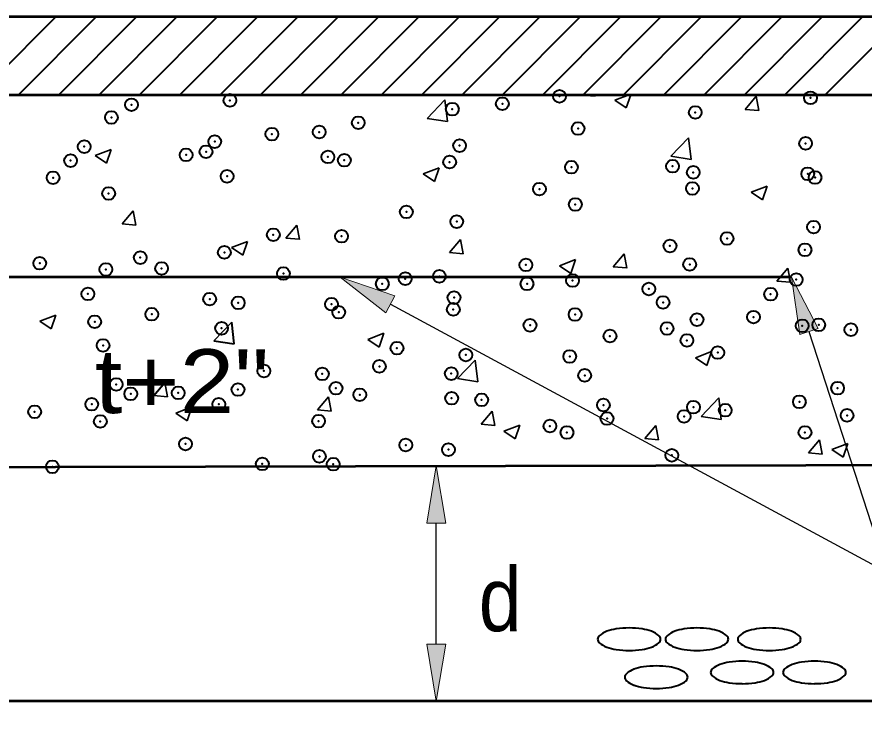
# Model space of a CAD drawing. Extents: x 36.4 to 71.7, y 0.5 to 22.5.
# Drawn here: x 50.926 to 52.782, y 8.551 to 10.106 of the extents above; entities that cross this region are included whole.
import ezdxf

# ---------------------------------------------------------------- set-up
doc = ezdxf.new("R2010")
doc.units = 0
doc.header["$LTSCALE"] = 0.056
doc.header["$PDMODE"] = 32
doc.header["$PDSIZE"] = 0.028
for name, color, linetype, lineweight in [('1', 7, 'Continuous', 40), ('3', 7, 'Continuous', 13), ('6', 7, 'Continuous', 13)]:
    doc.layers.add(name, color=color, linetype=linetype, lineweight=lineweight)

msp = doc.modelspace()

# ---------------------------------------------------------------- hatches: boundary and pattern name
at = {"layer": '1'}
for points in [[(51.86592, 8.99758), (51.82425, 8.99758), (51.84508, 9.12258), (51.84508, 9.12258)], [(51.86592, 8.73225), (51.82425, 8.73225), (51.84508, 8.60725), (51.84508, 8.60725)]]:
    msp.add_hatch(color=256, dxfattribs=at).paths.add_polyline_path(points)
at = {"layer": '3'}
for points in [[(51.73492, 9.45833), (51.75467, 9.495), (51.63483, 9.53608), (51.63483, 9.53608)], [(52.642, 9.41075), (52.68167, 9.42358), (52.62333, 9.53608), (52.62333, 9.53608)]]:
    msp.add_hatch(color=256, dxfattribs=at).paths.add_polyline_path(points)

# ---------------------------------------------------------------- linework, layer by layer
at = {"layer": '1', "lineweight": 53}
for p, q in [((53.64358, 10.10608), (47.51525, 10.10608)), ((47.58758, 9.9355), (53.64358, 9.9355)), ((52.62333, 9.53608), (48.61192, 9.53608)), ((53.64175, 8.60725), (50.02825, 8.60725))]:
    msp.add_line(p, q, dxfattribs=at)
at = {"layer": '1'}
for p, q in [((50.841, 9.9355), (51.01167, 10.10608)), ((50.92942, 9.9355), (51.1, 10.10608)), ((51.01783, 9.9355), (51.18842, 10.10608)), ((51.10617, 9.9355), (51.27683, 10.10608)), ((51.19458, 9.9355), (51.36517, 10.10608)), ((51.283, 9.9355), (51.45358, 10.10608)), ((51.37133, 9.9355), (51.54192, 10.10608)), ((51.45975, 9.9355), (51.63033, 10.10608)), ((51.54817, 9.9355), (51.71875, 10.10608)), ((51.6365, 9.9355), (51.80708, 10.10608)), ((51.72492, 9.9355), (51.8955, 10.10608)), ((51.81333, 9.9355), (51.98392, 10.10608)), ((51.90167, 9.9355), (52.07225, 10.10608)), ((51.99008, 9.9355), (52.16067, 10.10608)), ((52.0785, 9.9355), (52.24908, 10.10608)), ((52.16683, 9.9355), (52.33742, 10.10608)), ((52.25525, 9.9355), (52.42583, 10.10608)), ((52.34367, 9.9355), (52.51425, 10.10608)), ((52.432, 9.9355), (52.60258, 10.10608)), ((52.52042, 9.9355), (52.691, 10.10608)), ((52.60883, 9.9355), (52.77942, 10.10608)), ((52.69717, 9.9355), (52.86775, 10.10608)), ((51.4025, 9.38992), (51.39692, 9.43733)), ((51.358, 9.39675), (51.4025, 9.38992)), ((51.22658, 9.27683), (51.25067, 9.30558))]:
    msp.add_line(p, q, dxfattribs=at)
at = {"layer": '1', "lineweight": 35}
for p, q in [((52.16367, 9.93492), (52.16417, 9.9355)), ((52.16367, 9.93492), (52.19358, 9.93233)), ((52.19358, 9.93233), (52.193, 9.9355)), ((52.23667, 9.92358), (52.26758, 9.9355)), ((52.26158, 9.90683), (52.27117, 9.9355)), ((52.52233, 9.90358), (52.54642, 9.93225)), ((52.55225, 9.90092), (52.54642, 9.93225)), ((51.82533, 9.88383), (51.86425, 9.92442)), ((51.86983, 9.87692), (51.86425, 9.92442)), ((52.23667, 9.92358), (52.26158, 9.90683)), ((52.52233, 9.90358), (52.55217, 9.90092)), ((51.82533, 9.88383), (51.86983, 9.87692)), ((52.35892, 9.80108), (52.39792, 9.84167)), ((52.40342, 9.79417), (52.39792, 9.84167)), ((51.098, 9.80242), (51.133, 9.81583)), ((51.098, 9.80242), (51.12283, 9.78558)), ((51.12292, 9.78558), (51.133, 9.81583)), ((52.35892, 9.80108), (52.40342, 9.79417)), ((51.81658, 9.76233), (51.85158, 9.77575)), ((51.84142, 9.74558), (51.85158, 9.77575)), ((51.81658, 9.76233), (51.84142, 9.74558)), ((52.53517, 9.72233), (52.57017, 9.73575)), ((52.56, 9.7055), (52.57017, 9.73575)), ((52.53517, 9.72233), (52.56, 9.7055)), ((51.15717, 9.65292), (51.18125, 9.68167)), ((51.18708, 9.65033), (51.18125, 9.68167)), ((51.15717, 9.65292), (51.18708, 9.65033)), ((51.51583, 9.62158), (51.53992, 9.65033)), ((51.54567, 9.61892), (51.53992, 9.65033)), ((51.51583, 9.62158), (51.54567, 9.619)), ((51.87442, 9.59017), (51.8985, 9.61892)), ((51.90433, 9.58758), (51.89858, 9.61892)), ((51.39642, 9.60108), (51.4315, 9.6145)), ((51.39642, 9.60108), (51.42133, 9.58433)), ((51.42133, 9.58433), (51.4315, 9.6145)), ((51.87442, 9.59017), (51.90433, 9.58758)), ((52.23308, 9.55883), (52.25717, 9.58758)), ((52.26292, 9.55617), (52.25717, 9.58758)), ((52.115, 9.561), (52.15, 9.5745)), ((52.115, 9.561), (52.13992, 9.54425)), ((52.13992, 9.54425), (52.15, 9.5745)), ((52.23308, 9.55883), (52.26292, 9.55625)), ((52.59167, 9.52742), (52.61583, 9.55617)), ((52.62158, 9.52483), (52.61583, 9.55617)), ((52.59167, 9.52742), (52.62158, 9.52483)), ((50.97633, 9.43983), (51.01133, 9.45325)), ((51.00125, 9.423), (51.01133, 9.45325)), ((50.97633, 9.43983), (51.00125, 9.42308)), ((51.358, 9.39675), (51.39692, 9.43733)), ((51.69492, 9.39975), (51.72992, 9.41325)), ((51.71975, 9.383), (51.72992, 9.41317)), ((51.69492, 9.39975), (51.71975, 9.383)), ((52.4135, 9.35975), (52.4485, 9.37317)), ((52.4135, 9.35975), (52.43833, 9.34292)), ((52.43833, 9.34292), (52.4485, 9.37317)), ((51.89158, 9.314), (51.93058, 9.35458)), ((51.93608, 9.30708), (51.93058, 9.35458)), ((51.25642, 9.27425), (51.25067, 9.30558)), ((51.89158, 9.314), (51.93608, 9.30717)), ((51.22658, 9.27683), (51.25642, 9.27425)), ((51.58517, 9.2455), (51.60925, 9.27425)), ((51.61508, 9.24283), (51.60925, 9.27417)), ((52.42525, 9.23125), (52.46417, 9.27183)), ((52.46975, 9.22433), (52.46417, 9.27183)), ((51.27483, 9.2385), (51.30983, 9.25192)), ((51.29967, 9.22175), (51.30983, 9.25192)), ((51.58517, 9.2455), (51.61508, 9.24283)), ((51.27483, 9.2385), (51.29967, 9.22175)), ((51.94383, 9.21408), (51.96792, 9.24283)), ((51.97367, 9.2115), (51.96792, 9.24283)), ((51.97367, 9.2115), (51.96792, 9.24283)), ((52.42525, 9.23125), (52.46967, 9.22433)), ((51.94383, 9.21408), (51.97367, 9.2115)), ((51.99333, 9.1985), (52.02833, 9.21192)), ((52.01825, 9.18167), (52.02842, 9.21192)), ((52.01825, 9.18167), (52.02842, 9.21192)), ((52.30242, 9.18275), (52.32658, 9.2115)), ((52.33233, 9.18008), (52.32658, 9.21142)), ((51.99333, 9.1985), (52.01825, 9.18167)), ((52.30242, 9.18275), (52.33233, 9.18008)), ((52.66108, 9.15133), (52.68517, 9.18008)), ((52.691, 9.14875), (52.68517, 9.18008)), ((52.71192, 9.15842), (52.74692, 9.17183)), ((52.73683, 9.14167), (52.74692, 9.17183)), ((52.66108, 9.15133), (52.69092, 9.14875)), ((52.71192, 9.15842), (52.73683, 9.14167))]:
    msp.add_line(p, q, dxfattribs=at)
at = {"layer": '1', "lineweight": 13}
for p, q in [((51.86317, 9.12258), (51.66508, 9.12258)), ((51.80275, 8.60725), (51.66508, 8.60725))]:
    msp.add_line(p, q, dxfattribs=at)
at = {"layer": '1', "lineweight": 25}
msp.add_line((51.84508, 8.73225), (51.84508, 8.99758), dxfattribs=at)
at = {"layer": '1', "lineweight": 53}
msp.add_lwpolyline([(47.51525, 10.10608), (43.59017, 10.10608), (43.59017, 9.827), (43.43175, 9.55683), (43.67933, 9.42175), (43.62983, 9.27633), (44.10525, 9.27633), (46.07633, 9.11), (53.64175, 9.12625)], dxfattribs=at)
at = {"layer": '1', "lineweight": 13}
for points in [[(51.86592, 8.99758), (51.82425, 8.99758), (51.84508, 9.12258), (51.84508, 9.12258)], [(51.86592, 8.73225), (51.82425, 8.73225), (51.84508, 8.60725), (51.84508, 8.60725)]]:
    msp.add_lwpolyline(points, close=True, dxfattribs=at)
at = {"layer": '1'}
for centre, radius, start, end in [((52.25558, 8.6585), 0.10836, 98.47139, 109.71022), ((52.26783, 8.57525), 0.19248, 90.02264, 98.43766), ((52.26775, 8.57467), 0.19304, 81.57477, 89.98979), ((52.28, 8.65892), 0.10795, 70.23479, 81.47362), ((52.40408, 8.65892), 0.10795, 98.52638, 109.76521), ((52.41633, 8.57467), 0.19304, 90.0102, 98.42523), ((52.41625, 8.57525), 0.19248, 81.56233, 89.97736), ((52.4285, 8.6585), 0.10836, 70.28977, 81.5286), ((52.56258, 8.6585), 0.10836, 98.47139, 109.71022), ((52.57483, 8.57467), 0.19304, 90.0102, 98.42523), ((52.57475, 8.57525), 0.19248, 81.56233, 89.97736), ((52.587, 8.6585), 0.10836, 70.28977, 81.5286), ((52.209, 8.74308), 0.01025, 130.57008, 179.80152), ((52.20892, 8.74317), 0.01016, 180.43525, 229.6667), ((52.23658, 8.71092), 0.05258, 109.55636, 130.6711), ((52.29892, 8.71092), 0.05258, 49.32889, 70.44364), ((52.32658, 8.74317), 0.01016, 310.3333, 359.56474), ((52.3265, 8.74308), 0.01025, 0.19847, 49.42992), ((52.35758, 8.74308), 0.01025, 130.57008, 179.80152), ((52.3575, 8.74317), 0.01016, 180.43525, 229.6667), ((52.38517, 8.71092), 0.05258, 109.55636, 130.6711), ((52.4475, 8.71092), 0.05258, 49.32889, 70.44364), ((52.47508, 8.74308), 0.01025, 0.19847, 49.42992), ((52.47517, 8.74317), 0.01016, 310.3333, 359.56474), ((52.516, 8.74317), 0.01021, 131.07972, 180.31117), ((52.51592, 8.74308), 0.01012, 179.922, 229.15345), ((52.54358, 8.71092), 0.05258, 109.55636, 130.6711), ((52.606, 8.71092), 0.05258, 49.32889, 70.44364), ((52.63358, 8.74317), 0.01021, 359.68883, 48.92027), ((52.63367, 8.74308), 0.01012, 310.84655, 0.07799), ((52.23683, 8.77525), 0.05269, 229.11499, 250.22974), ((52.25508, 8.82775), 0.10826, 250.5082, 261.74703), ((52.28042, 8.82733), 0.10785, 278.30717, 289.546), ((52.29867, 8.77525), 0.05269, 289.77026, 310.885), ((52.38542, 8.77525), 0.05269, 229.11499, 250.22974), ((52.40367, 8.82733), 0.10785, 250.454, 261.69283), ((52.429, 8.82775), 0.10826, 278.25297, 289.4918), ((52.44725, 8.77525), 0.05269, 289.77026, 310.885), ((52.54383, 8.77525), 0.05269, 229.11499, 250.22974), ((52.56208, 8.82775), 0.10826, 250.5082, 261.74703), ((52.5875, 8.82775), 0.10826, 278.25297, 289.4918), ((52.60575, 8.77525), 0.05269, 289.77026, 310.885), ((52.26783, 8.911), 0.19248, 261.56233, 269.97736), ((52.26775, 8.91158), 0.19304, 270.0102, 278.42523), ((52.41633, 8.91158), 0.19304, 261.57477, 269.98979), ((52.41625, 8.911), 0.19248, 270.02264, 278.43766), ((52.57483, 8.91158), 0.19304, 261.57477, 269.98979), ((52.57475, 8.911), 0.19248, 270.02264, 278.43766), ((52.48417, 8.63817), 0.05258, 109.55636, 130.6711), ((52.50317, 8.58575), 0.10836, 98.47139, 109.71022), ((52.51542, 8.50192), 0.19304, 90.0102, 98.42523), ((52.51533, 8.5025), 0.19248, 81.56233, 89.97736), ((52.52758, 8.58575), 0.10836, 70.28977, 81.5286), ((52.54658, 8.63817), 0.05258, 49.32889, 70.44364), ((52.64267, 8.63817), 0.05258, 109.55636, 130.6711), ((52.66167, 8.58575), 0.10836, 98.47139, 109.71022), ((52.67392, 8.5025), 0.19248, 90.02264, 98.43766), ((52.67383, 8.50192), 0.19304, 81.57477, 89.98979), ((52.68608, 8.58617), 0.10795, 70.23479, 81.47362), ((52.705, 8.63817), 0.05258, 49.32889, 70.44364), ((52.29625, 8.62783), 0.05269, 109.77026, 130.885), ((52.3145, 8.57533), 0.10826, 98.25297, 109.4918), ((52.32725, 8.49208), 0.19248, 90.02264, 98.43766), ((52.32717, 8.4915), 0.19304, 81.57477, 89.98979), ((52.33983, 8.57575), 0.10785, 70.454, 81.69283), ((52.35808, 8.62783), 0.05269, 49.11499, 70.22974), ((52.45658, 8.67042), 0.01021, 131.07972, 180.31117), ((52.4565, 8.67033), 0.01012, 179.922, 229.15345), ((52.57425, 8.67033), 0.01012, 310.84655, 0.07799), ((52.57417, 8.67042), 0.01021, 359.68883, 48.92027), ((52.61508, 8.67042), 0.01021, 131.07972, 180.31117), ((52.615, 8.67033), 0.01012, 179.922, 229.15345), ((52.73258, 8.67033), 0.01025, 0.19847, 49.42992), ((52.73267, 8.67042), 0.01016, 310.3333, 359.56474), ((52.26833, 8.66), 0.01012, 130.84655, 180.07799), ((52.26842, 8.65992), 0.01021, 179.68883, 228.92027), ((52.296, 8.69217), 0.05258, 229.32889, 250.44364), ((52.35833, 8.69217), 0.05258, 289.55636, 310.6711), ((52.386, 8.65992), 0.01016, 0.43525, 49.6667), ((52.38592, 8.66), 0.01025, 310.57008, 359.80152), ((52.48442, 8.7025), 0.05269, 229.11499, 250.22974), ((52.50267, 8.755), 0.10826, 250.5082, 261.74703), ((52.52808, 8.755), 0.10826, 278.25297, 289.4918), ((52.54633, 8.7025), 0.05269, 289.77026, 310.885), ((52.64292, 8.7025), 0.05269, 229.11499, 250.22974), ((52.66117, 8.755), 0.10826, 250.5082, 261.74703), ((52.6865, 8.75458), 0.10785, 278.30717, 289.546), ((52.70475, 8.7025), 0.05269, 289.77026, 310.885), ((52.315, 8.74458), 0.10836, 250.28977, 261.5286), ((52.32725, 8.82783), 0.19248, 261.56233, 269.97736), ((52.32717, 8.82842), 0.19304, 270.0102, 278.42523), ((52.33942, 8.74417), 0.10795, 278.52638, 289.76521), ((52.51542, 8.83883), 0.19304, 261.57477, 269.98979), ((52.51533, 8.83825), 0.19248, 270.02264, 278.43766), ((52.67392, 8.83825), 0.19248, 261.56233, 269.97736), ((52.67383, 8.83883), 0.19304, 270.0102, 278.42523)]:
    msp.add_arc(centre, radius, start, end, dxfattribs=at)
for p in [(51.393, 9.92342), (52.11517, 9.93233), (52.66517, 9.92892), (51.17733, 9.91375), (51.88033, 9.90408), (51.99, 9.91592), (51.13333, 9.88592), (52.41258, 9.89692), (51.67425, 9.87433), (52.15592, 9.86167), (51.48492, 9.84942), (51.58867, 9.854), (51.35975, 9.83292), (51.89617, 9.82417), (52.65442, 9.82917), (51.07375, 9.82208), (51.34067, 9.81083), (51.04392, 9.79133), (51.29708, 9.804), (51.60758, 9.7995), (51.64367, 9.79217), (51.8745, 9.78825), (52.14133, 9.777), (52.36283, 9.77917), (51.0055, 9.75392), (51.38692, 9.757), (52.40825, 9.76567), (52.65908, 9.76242), (52.67517, 9.75442), (51.12725, 9.7195), (52.07125, 9.72908), (52.4065, 9.73042), (52.14983, 9.69525), (51.77967, 9.679), (51.89008, 9.65775), (52.67183, 9.64583), (51.48808, 9.629), (51.63758, 9.62575), (52.48242, 9.62092), (52.35725, 9.6045), (51.38083, 9.5905), (52.653, 9.596), (50.97633, 9.56658), (51.1965, 9.57892), (52.40042, 9.564), (51.12117, 9.553), (51.24325, 9.55533), (52.0415, 9.56292), (51.51017, 9.54408), (51.77708, 9.53275), (51.85208, 9.53792), (52.14375, 9.52875), (52.63383, 9.53083), (51.72692, 9.5215), (52.044, 9.5215), (52.31092, 9.51025), (51.08175, 9.49942), (51.884, 9.49133), (52.57783, 9.49892), (51.34867, 9.48817), (51.41117, 9.47992), (51.61558, 9.47692), (52.34217, 9.48083), (51.22183, 9.455), (51.6315, 9.45925), (51.8825, 9.46558), (52.14942, 9.45433), (51.09667, 9.4385), (52.41633, 9.44308), (52.54025, 9.44867), (51.37475, 9.42408), (52.05058, 9.43075), (52.35092, 9.42375), (52.64692, 9.42958), (52.68325, 9.43175), (52.75358, 9.42108), (52.22575, 9.40725), (52.39433, 9.39758), (51.11508, 9.38658), (51.759, 9.38067), (51.90992, 9.36567), (52.13767, 9.36233), (52.462, 9.371), (51.46742, 9.33067), (51.59542, 9.32425), (51.72058, 9.34075), (51.87792, 9.32483), (52.17042, 9.321), (51.14383, 9.30117), (51.41067, 9.28992), (51.62542, 9.29283), (52.7245, 9.293), (51.17583, 9.28058), (51.27967, 9.28267), (51.67758, 9.27858), (51.87883, 9.27092), (51.9445, 9.26733), (51.09025, 9.25775), (51.36867, 9.25767), (52.21142, 9.25608), (52.40875, 9.25142), (52.64083, 9.26308), (50.96508, 9.24125), (52.38825, 9.23108), (52.47833, 9.24475), (52.74525, 9.2335), (51.109, 9.22017), (51.58725, 9.22083), (52.21933, 9.2265), (52.09417, 9.21008), (52.13158, 9.19592), (52.653, 9.19608), (51.29567, 9.17083), (51.77842, 9.1685), (51.87183, 9.15842), (51.58908, 9.14358), (52.36133, 9.146), (51.00408, 9.12075), (51.46392, 9.12708), (51.61933, 9.12642)]:
    msp.add_point(p, dxfattribs=at)
at = {"layer": '3', "lineweight": 25}
for p, q in [((51.74483, 9.47667), (52.8325, 8.88958)), ((52.66183, 9.41717), (53.0585, 8.19075))]:
    msp.add_line(p, q, dxfattribs=at)
at = {"layer": '3'}
for points in [[(51.73492, 9.45833), (51.75467, 9.495), (51.63483, 9.53608), (51.63483, 9.53608)], [(52.642, 9.41075), (52.68167, 9.42358), (52.62333, 9.53608), (52.62333, 9.53608)]]:
    msp.add_lwpolyline(points, close=True, dxfattribs=at)
at = {"layer": '6'}
for p, q in [((51.84508, 9.12258), (51.84517, 9.12258)), ((51.92567, 9.12258), (51.92575, 9.12258)), ((51.86525, 8.60725), (51.86533, 8.60725))]:
    msp.add_line(p, q, dxfattribs=at)

# ---------------------------------------------------------------- texts
at = {"layer": '3'}
for s, width, p in [('t+2"', 1.15, (51.09733, 9.23825)), ('d', 0.9, (51.93833, 8.76067))]:
    msp.add_text(s, height=0.14, dxfattribs=dict(at, width=width)).set_placement(p)

doc.saveas('drawing.dxf')
